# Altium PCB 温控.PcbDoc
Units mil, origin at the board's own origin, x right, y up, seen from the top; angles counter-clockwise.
Board outline 2221.1 x 1417.32 mil, 2 copper layers (Top Layer, Bottom Layer); 14 components, 17 nets, 78 pads, 12 vias.
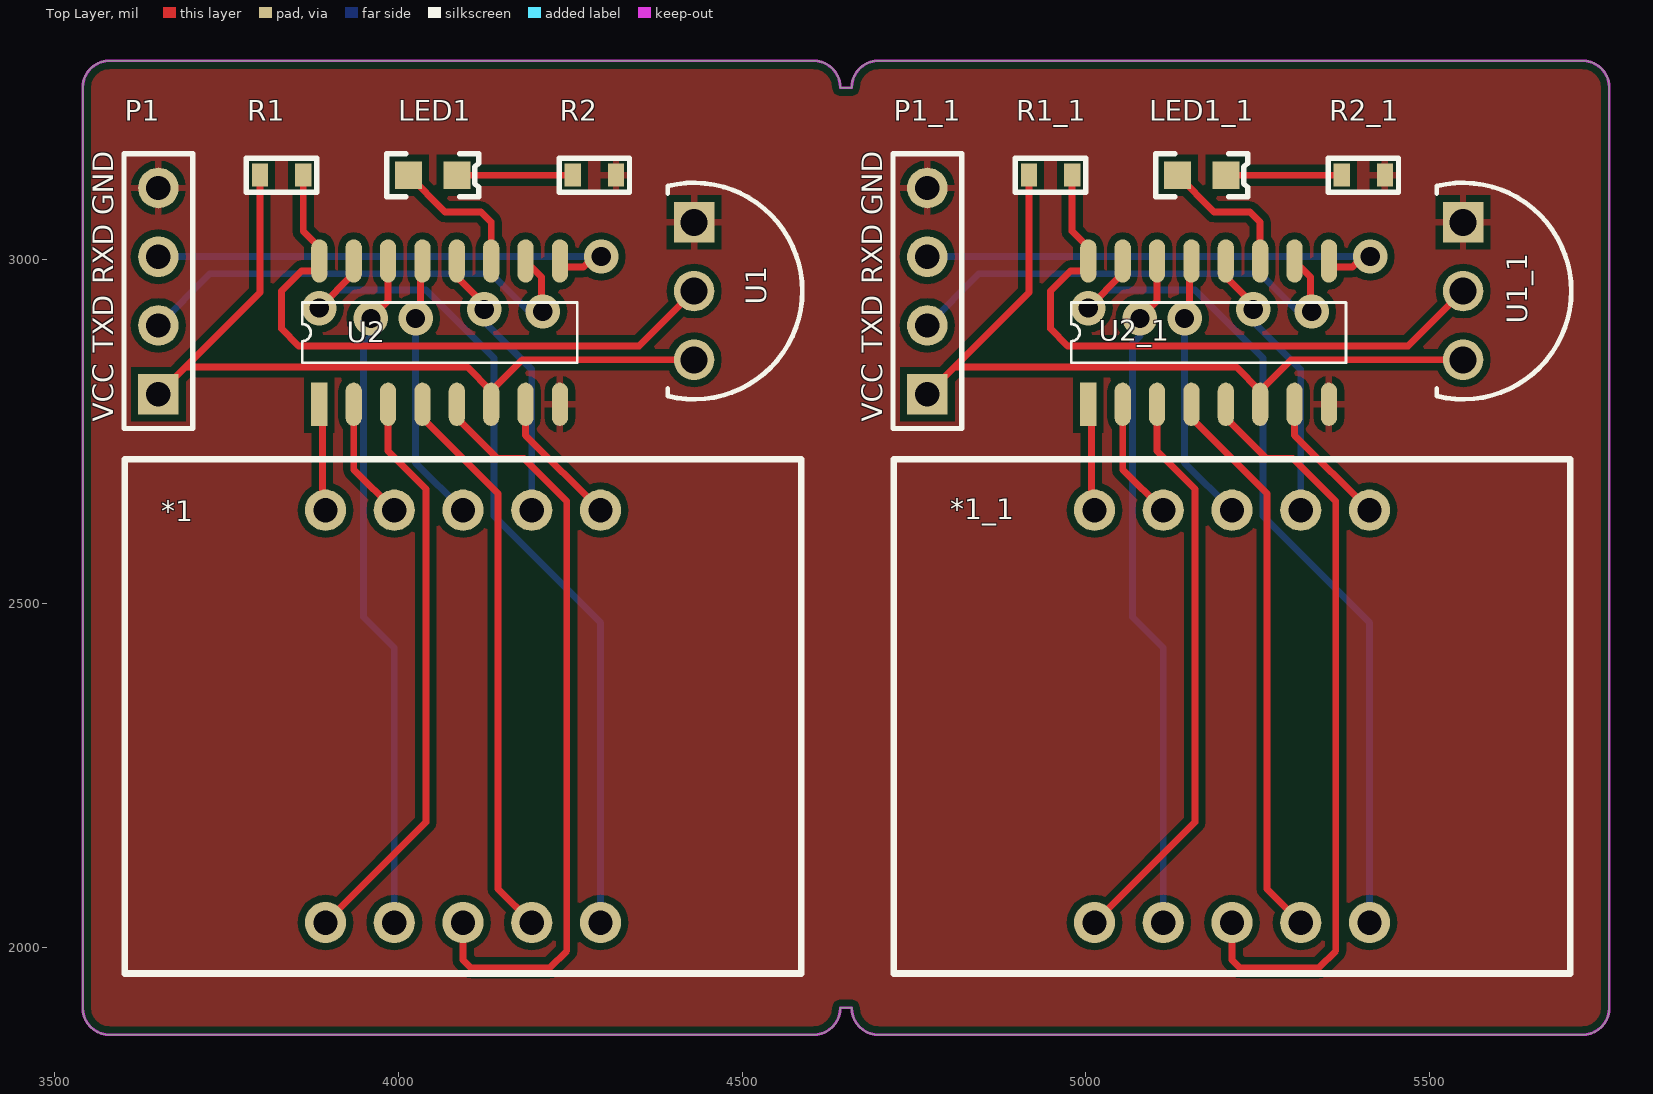
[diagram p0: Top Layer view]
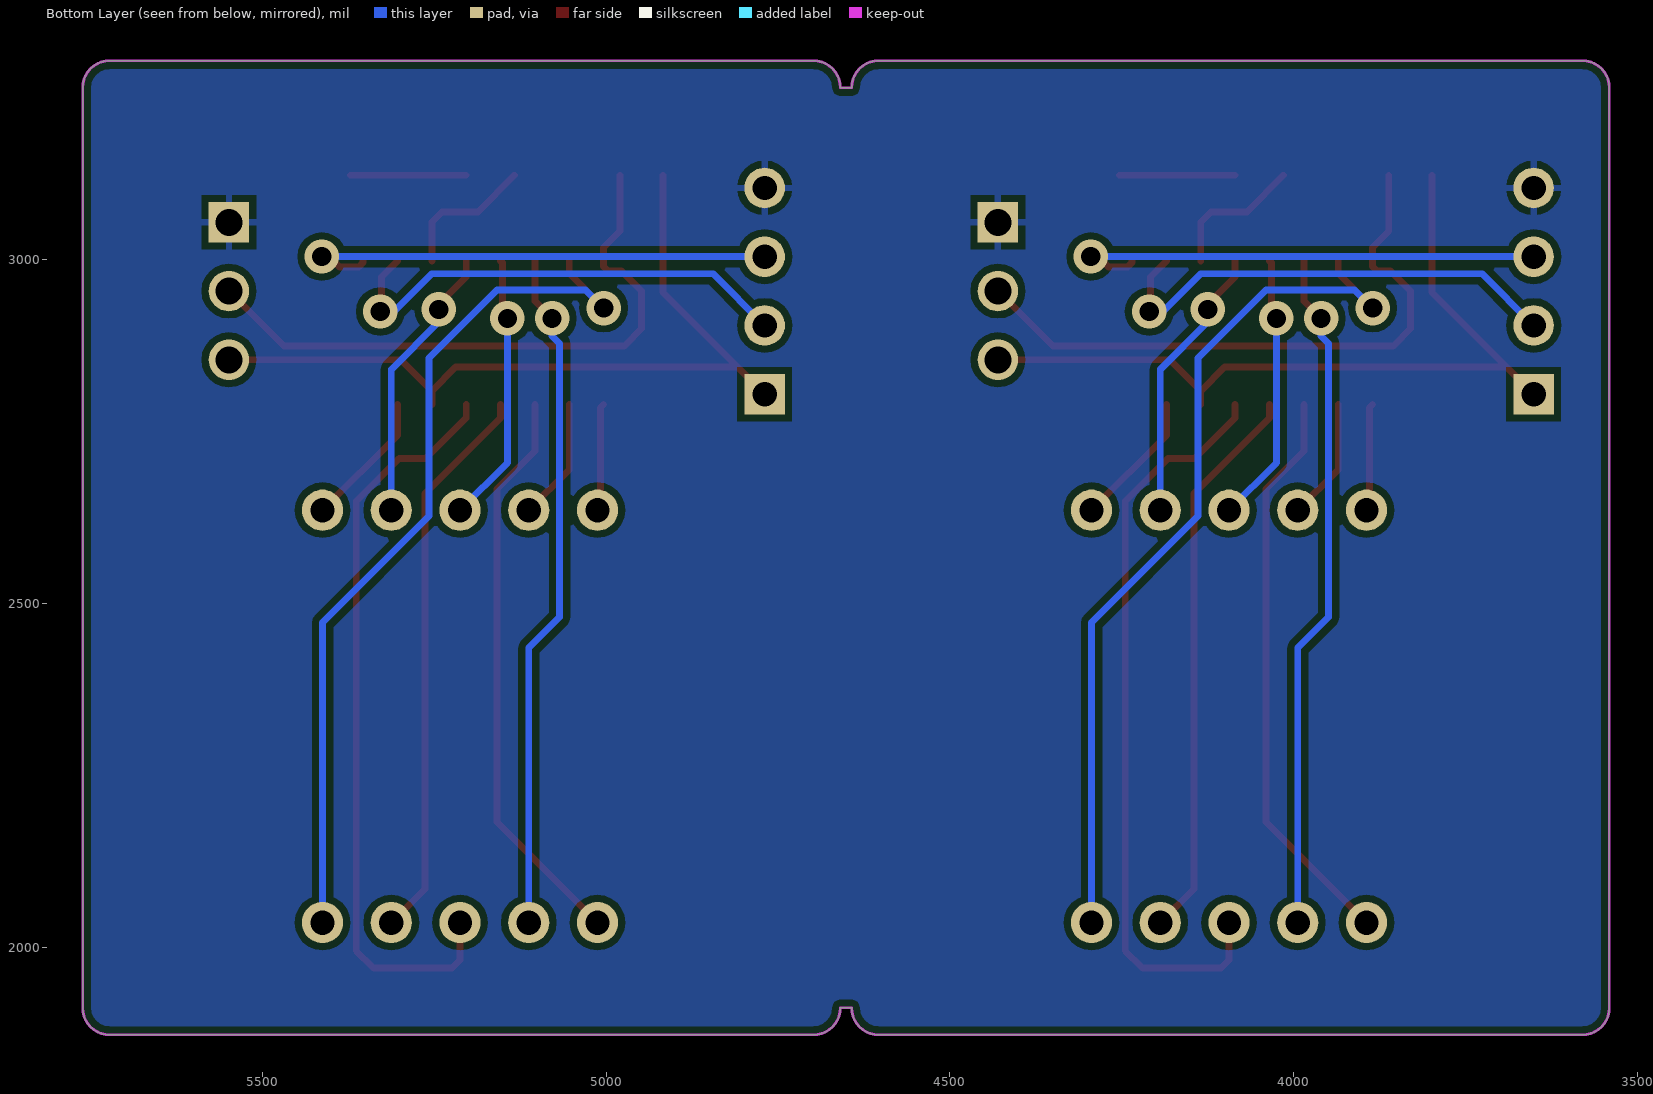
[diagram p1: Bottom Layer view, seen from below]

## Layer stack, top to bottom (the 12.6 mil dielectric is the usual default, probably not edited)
Top Solder: solder mask 0.4, Solder Resist, Dk 3.5
Top Layer: signal copper 1.4
Dielectric 1: dielectric 12.6, FR-4, Dk 4.8
Bottom Layer: signal copper 1.4
Bottom Solder: solder mask 0.4, Solder Resist, Dk 3.5

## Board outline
3580,1872.68 4603.62,1872.68 ccw(c4603.62,1912.05) 4642.99,1912.05 4659.37,1912.05 ccw(c4698.74,1912.05) 4698.74,1872.68 5722.36,1872.68 ccw(c5722.36,1912.05) 5761.73,1912.05 5761.73,3250.63 ccw(c5722.36,3250.63) 5722.36,3290 4698.74,3290 ccw(c4698.74,3250.63) 4659.37,3250.63 4642.99,3250.63 ccw(c4603.62,3250.63) 4603.62,3290 3580,3290 ccw(c3580,3250.63) 3540.63,3250.63 3540.63,1912.05 ccw(c3580,1912.05)

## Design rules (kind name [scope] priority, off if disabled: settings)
Clearance [All] p1: gap=10 ignorepadtopadclearanceinfootprint=FALSE except(0: Arc-Hole Track-Hole SMDPad-Hole THPad-Hole Via-Hole Fill-Hole Poly-Hole Region-Hole Text-Hole)
PolygonConnect [All] p1: connectstyle=Relief reliefconductorwidth=10 reliefentries=4 polygonreliefangle="90 Angle" airgapwidth=10
RoutingVias [All] p1: holewidth=28 width=50 viastyle="Through Hole" minholewidth=28 minwidth=50 maxholewidth=28 maxwidth=50
SolderMaskExpansion [All] p1: expansion=4 istentingtop=FALSE
Width [All] p1: maxlimit=10 minlimit=10 preferedwidth=10
30 further rules are at their usual default settings.

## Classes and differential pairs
component class 温控: *1 LED1 P1 R1 R2 U1 U2

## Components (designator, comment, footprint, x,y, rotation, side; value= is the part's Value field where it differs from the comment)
*1 "Digital" Digital 4100,2330 r0 top
*1_1 "Digital" Digital 5218.74,2330 r0 top (schematic designator *1)
LED1 "BLUE" LED_0603 4050,3123.28 r0 top
LED1_1 "BLUE" LED_0603 5168.74,3123.28 r0 top (schematic designator LED1)
P1 "Header 4" HDR1X4 3650.81,2804.78 r90 top
P1_1 "Header 4" HDR1X4 4769.55,2804.78 r90 top (schematic designator P1)
R1 "10K" C_0603_L 3830,3123.28 r180 top
R1_1 "10K" C_0603_L 4948.74,3123.28 r180 top (schematic designator R1)
R2 "10K" C_0603_L 4285,3123.28 r0 top
R2_1 "10K" C_0603_L 5403.74,3123.28 r0 top (schematic designator R2)
U1 "DS18B20" DS18B20 4430.15,2954.78 r270 top
U1_1 "DS18B20" DS18B20 5548.89,2954.78 r270 top (schematic designator U1)
U2 "STC15W408AD_SOP16_DIP16" SOP16 3885,2790 r90 top
U2_1 "STC15W408AD_SOP16_DIP16" SOP16 5003.74,2790 r90 top (schematic designator U2)

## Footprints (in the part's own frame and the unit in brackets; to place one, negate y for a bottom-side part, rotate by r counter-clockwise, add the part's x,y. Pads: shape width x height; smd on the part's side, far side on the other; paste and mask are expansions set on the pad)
C_0603_L [mm]
  rect 0.6x0.85 smd: 1(-0.8,0) 2(0.8,0)
  silkscreen extent -1.3,-0.63 1.3,0.63, body extent -0.8,-0.4 0.8,0.4, height 0.6
Digital [mil] "数码管"
  round 60 hole 35.43: 1(-206,-294) 2(-106,-294) 3(-6,-294) 4(94,-294) 5(194,-294) 6(194,306) 7(94,306) 8(-6,306) 9(-106,306) 10(-206,306)
  silkscreen extent -498,-368 486,380
DS18B20 [mm] "DS18B20"
  rect 1.5x1.5 hole 1: 1(-2.54,0)
  round 1.5 hole 1: 2(0,0) 3(2.54,0)
  silkscreen extent -4,-0.97 4,4
HDR1X4 [mm] "Connector; Header; 4 Position"
  rect 1.5x1.5 hole 0.9: 1(0,0)
  round 1.5 hole 0.9: 2(2.54,0) 3(5.08,0) 4(7.62,0)
  silkscreen extent -1.27,-1.27 8.89,1.27
LED_0603 [mm]
  rect 1x1 smd: 1(-0.9,0) 2(0.9,0)
  silkscreen extent -1.7,-0.8 1.7,0.8, body extent -0.81,-0.37 0.84,0.36, height 0.68
SOP16 [mm]
  rect 1.6x0.6 smd: 1(0,0)
  oval 1.6x0.6 smd: 2(0,-1.27) 3(0,-2.54) 4(0,-3.81) 5(0,-5.08) 6(0,-6.35) 7(0,-7.62) 8(0,-8.89) 9(5.3,-8.89) 10(5.3,-7.62) 11(5.3,-6.35) 12(5.3,-5.08) 13(5.3,-3.81) 14(5.3,-2.54) 15(5.3,-1.27) 16(5.3,0)
  silkscreen extent 1.53,-9.53 3.77,0.64

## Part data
*1 *1_1: "数码管"
LED1 LED1_1: library part D_LED_0603
P1 P1_1: "Header, 4-Pin"
R1 R1_1 R2 R2_1: library part R_0603

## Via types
v1: diameter 50, hole 28, Top Layer to Bottom Layer, 12 vias

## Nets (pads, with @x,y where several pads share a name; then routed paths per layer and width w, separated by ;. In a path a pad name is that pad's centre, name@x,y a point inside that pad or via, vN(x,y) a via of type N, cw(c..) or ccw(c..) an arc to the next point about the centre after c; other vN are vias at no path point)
DIGITAL_1: *1.10 U2.1 | length 157.7
  Top Layer w10: U2.1 3889.5,2785.5 3889.5,2640.5 *1.10
DIGITAL_2: *1.9 U2.2 | length 178.4
  Top Layer w10: U2.2 3935,2695 *1.9
DIGITAL_3: *1.1 U2.3 | length 837.3
  Top Layer w10: *1.1 4040,2182 4040,2667.01 3985,2722.01 U2.3
DIGITAL_4: *1.4 U2.4 | length 819.9
  Top Layer w10: U2.4 4035,2770.31 4145,2660.31 4145,2085 *1.4
DIGITAL_5: *1.3 U2.5 | length 1104.1
  Top Layer w10: U2.5 4085,2770.31 4144.14,2711.17 4182.47,2711.17 4245,2648.64 4245,1995 4220,1970 4105.86,1970 4094,1981.86 *1.3
DIGITAL_6: *1.6 U2.7 | length 199.1
  Top Layer w10: U2.7 4185,2745 *1.6
DIGITAL_7: *1.5 U2.15 | length 1281
  Top Layer w10: v1(3885,2930) 3935,2980 U2.15
  Bottom Layer w10: v1(3885,2930) 3911.4,2956.4 4040.16,2956.4 4065,2931.57 4139,2857.57 4139,2627.36 4294,2472.36 *1.5
DIGITAL_8: *1.2 U2.14 | length 996.2
  Top Layer w10: v1(3960,2915) 3985,2940 U2.14
  Bottom Layer w10: v1(3960,2915) 3960,2889.48 3949,2878.48 3949,2480.27 3994,2435.27 *1.2
DIGITAL_9: *1.8 U2.13 | length 395.4
  Top Layer w10: v1(4025,2915) 4032.39,2922.39 4032.39,2996.05 U2.13
  Bottom Layer w10: v1(4025,2915) 4025,2705 *1.8
DIGITAL_10: *1.7 U2.12 | length 407.8
  Top Layer w10: U2.12 4085,2975.29 4125.03,2935.26 v1(4125.03,2928.11)
  Bottom Layer w10: v1@4125,2920 4125,2910 4194,2841 *1.7 ; v1@4125.03,2920.03 v1(4125.03,2928.11)
GND: P1.4 P1_1.4 R2.2 R2_1.2 U1.1 U1_1.1 U2.8 U2_1.8
LED: LED1.1 U2.11 | length 205.1
  Top Layer w10: LED1.1 4067.85,3070 4120,3070 4135,3055 U2.11
NetLED1_2: LED1.2 R2.1 | length 168.1
  Top Layer w10: LED1.2 R2.1
NetR1_1: R1.1 U1.2 U2.16 | length 910.9
  Top Layer w10: R1.1 3861.5,3041.85 3885,3018.35 3885,2990.27 3878.71,2983.98 3858.98,2983.98 3830,2955 3830,2900 3855,2875 4350.37,2875 U1.2
RXD: P1.3 U2.9 | length 715.5
  Top Layer w10: U2.9 4235,2996.29 4241.29,2990 4269.18,2990 4284.18,3005 v1(4295,3005)
  Bottom Layer w10: P1.3 3650.92,3004.89 4294.89,3004.89 v1(4295,3005)
TXD: P1.2 U2.10 | length 697.1
  Top Layer w10: U2.10 4208.19,2975.47 4208.19,2926.81 v1(4210,2925)
  Bottom Layer w10: P1.2 3726.03,2980 4135,2980 4190,2925 v1(4210,2925)
VCC: P1.1 R1.2 U1.3 U2.6 | length 1172.1
  Top Layer w10: P1.1 3690.52,2844.48 ; R1.2 3798.5,2952.47 3690.52,2844.48 ; U2.6 U2.6@4135,2809.69 ; U1.3 4180.09,2854.78 U2.6@4135,2809.69 ; 3690.52,2844.48 4100.2,2844.48 U2.6@4135,2809.69
pads on no net: *1_1.1 *1_1.2 *1_1.3 *1_1.4 *1_1.5 *1_1.6 *1_1.7 *1_1.8 *1_1.9 *1_1.10 LED1_1.1 LED1_1.2 P1_1.1 P1_1.2 P1_1.3 R1_1.1 R1_1.2 R2_1.1 U1_1.2 U1_1.3 U2_1.1 U2_1.2 U2_1.3 U2_1.4 U2_1.5 U2_1.6 U2_1.7 U2_1.9 U2_1.10 U2_1.11 U2_1.12 U2_1.13 U2_1.14 U2_1.15 U2_1.16
copper on no net: | length 10245.8
  Top Layer w10: 4769.55,2804.78 4809.26,2844.48 ; 4917.24,3123.28 4917.24,2952.47 4809.26,2844.48 ; 4980.24,3123.28 4980.24,3041.85 5003.74,3018.35 5003.74,2990.27 4997.45,2983.98 4977.72,2983.98 4948.74,2955 4948.74,2900 4973.74,2875 5469.11,2875 5548.89,2954.78 ; 5003.74,2790 5008.24,2785.5 5008.24,2640.5 5012.74,2636 ; v1(5003.74,2930) 5053.74,2980 5053.74,2998.66 ; 5012.74,2036 5158.74,2182 5158.74,2667.01 5103.74,2722.01 5103.74,2790 ; 5053.74,2790 5053.74,2695 5112.74,2636 ; v1(5078.74,2915) 5103.74,2940 5103.74,2998.66 ; 5133.31,3123.28 5186.59,3070 5238.74,3070 5253.74,3055 5253.74,2998.66 ; v1(5143.74,2915) 5151.13,2922.39 5151.13,2996.05 5153.74,2998.66 ; 5153.74,2790 5153.74,2770.31 5263.74,2660.31 5263.74,2085 5312.74,2036 ; 5203.74,2790 5203.74,2770.31 5262.88,2711.17 5301.21,2711.17 5363.74,2648.64 5363.74,1995 5338.74,1970 5224.6,1970 5212.74,1981.86 5212.74,2036 ; 5203.74,2998.66 5203.74,2975.29 5243.77,2935.26 v1(5243.77,2928.11) ; 5204.17,3123.28 5372.24,3123.28 ; 5253.74,2790 5253.74,2809.69 ; 5303.74,2790 5303.74,2745 5412.74,2636 ; 5303.74,2998.66 5326.93,2975.47 5326.93,2926.81 v1(5328.74,2925) ; 5353.74,2998.66 5353.74,2996.29 5360.03,2990 5387.92,2990 5402.92,3005 v1(5413.74,3005) ; 5548.89,2854.78 5298.83,2854.78 5253.74,2809.69 ; 4809.26,2844.48 5218.94,2844.48 5253.74,2809.69
  Bottom Layer w10: 4769.55,2904.78 4844.77,2980 5253.74,2980 5308.74,2925 v1(5328.74,2925) ; 4769.55,3004.78 4769.66,3004.89 5413.63,3004.89 v1(5413.74,3005) ; v1(5003.74,2930) 5030.14,2956.4 5158.9,2956.4 5183.74,2931.57 5257.74,2857.57 5257.74,2627.36 5412.74,2472.36 5412.74,2036 ; v1(5078.74,2915) 5078.74,2889.48 5067.74,2878.48 5067.74,2480.27 5112.74,2435.27 5112.74,2036 ; v1(5143.74,2915) 5143.74,2705 5212.74,2636 ; v1@5243.74,2920 5243.74,2910 5312.74,2841 5312.74,2636 ; v1@5243.77,2920.03 v1(5243.77,2928.11)

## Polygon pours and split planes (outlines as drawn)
GND on Top Layer "Top Layer-No Net" (solid, remove dead copper, pour order 0): 3580,1872.68 4603.62,1872.68 ccw(c4603.62,1912.05) 4642.99,1912.05 4659.37,1912.05 ccw(c4698.74,1912.05) 4698.74,1872.68 5722.36,1872.68 ccw(c5722.36,1912.05) 5761.73,1912.05 5761.73,3250.63 ccw(c5722.36,3250.63) 5722.36,3290 4698.74,3290 ccw(c4698.74,3250.63) 4659.37,3250.63 4642.99,3250.63 ccw(c4603.62,3250.63) 4603.62,3290 3580,3290 ccw(c3580,3250.63) 3540.63,3250.63 3540.63,1912.05 ccw(c3580,1912.05)
GND on Bottom Layer "Top Layer-No Net1" (solid, remove dead copper, pour order 1): 3580,1872.68 4603.62,1872.68 ccw(c4603.62,1912.05) 4642.99,1912.05 4659.37,1912.05 ccw(c4698.74,1912.05) 4698.74,1872.68 5722.36,1872.68 ccw(c5722.36,1912.05) 5761.73,1912.05 5761.73,3250.63 ccw(c5722.36,3250.63) 5722.36,3290 4698.74,3290 ccw(c4698.74,3250.63) 4659.37,3250.63 4642.99,3250.63 ccw(c4603.62,3250.63) 4603.62,3290 3580,3290 ccw(c3580,3250.63) 3540.63,3250.63 3540.63,1912.05 ccw(c3580,1912.05)

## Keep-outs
Keep-Out Layer:
  the board outline again, w3.94

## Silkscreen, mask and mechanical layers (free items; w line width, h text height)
Top Overlay:
  text "GND" at 3585,3064.79 h30 r90
  text "GND" at 4703.74,3064.79 h30 r90
  text "RXD" at 3585,2964.79 h30 r90
  text "RXD" at 4703.74,2964.79 h30 r90
  text "TXD" at 3585,2864.79 h30 r90
  text "TXD" at 4703.74,2864.79 h30 r90
  text "VCC" at 3585,2764.79 h30 r90
  text "VCC" at 4703.74,2764.79 h30 r90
